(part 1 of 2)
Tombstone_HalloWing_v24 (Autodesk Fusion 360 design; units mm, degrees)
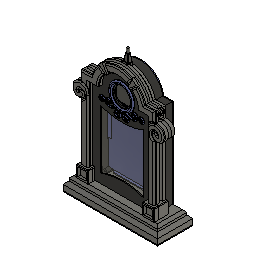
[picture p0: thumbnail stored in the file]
part number: FIDUCIAL_1MM
part number: MOUNTINGHOLE2.5
part number: SEWTAP_ALLILONG
part number: SEWTAPPCB_ALLIGATOR
part number: ALS-PT21
part number: 1M
part number: EAGLE
part number: ORANGE
part number: SPST_TACT-EVQQ2
part number: microUSB
part number: MCP73831T-2ACI/OT
part number: JSTPH
part number: WS2812B_4020
part number: FEATHERWING_SMTDUALNOHOLES
part number: BSS138
part number: JST PH 3
part number: MBR0540
part number: DMG3405
part number: 10K
part number: JST PH 4
parameter "wallThickness" = 1.5
parameter "M3hole" = 3
parameter "m25" = 2.5
parameter "gap" = 0.2
parameter "acrylicThickness" = 3
work_plane "WorkPlane1" AlongDistance -2
sketch "base profile" plane through (0, -2, 0) normal (0, 1, 0) x axis (1, 0, 0)
  line L1 (80, -14) -> (-80, -14)
  line L2 (80, 0) -> (80, -14)
  line L3 (-80, 0) -> (80, 0)
  line L4 (-80, -14) -> (-80, 0)
  line L5 (75, -22) -> (-75, -22)
  line L6 (75, -14) -> (75, -22)
  line L7 (-75, -14) -> (75, -14)
  line L8 (-75, -22) -> (-75, -14)
  line L9 (34, -168) -> (-34, -168)
  line L10 (-50, -168) -> (-34, -168)
  line L11 (-50, -22) -> (-50, -168)
  line L12 (0, -22) -> (0, -202)
  line L13 (50, -168) -> (34, -168)
  line L14 (50, -22) -> (50, -168)
  curve K1 (0, -153) -> (0, -183)
  curve K2 (-14, -168) -> (14, -168)
  arc A1 centre (0, -168) radius 34 clockwise from (34, -168) to (-34, -168)
  closed curve K3 centre (0, -168)
  point P1 (0, 0)
  point P14 (-50, -22)
  point P15 (0, -202)
  point P16 (0, -22)
  point P12 (0, -168)
  point P18 (50, -22)
  point P20 (0, -183)
  point P21 (0, -153)
  point P22 (14, -168)
  point P23 (-14, -168)
  point P4 (80, 0)
  point P5 (-80, 0)
  point P3 (80, -14)
  point P7 (75, -22)
  point P8 (75, -14)
  point P10 (-34, -168)
  point P13 (-50, -168)
  horizontal L1
  vertical L2
  horizontal L3
  vertical L4
  horizontal L5
  vertical L6
  horizontal L7
  vertical L8
  midpoint L1 L7
  midpoint P1 L3
  horizontal L9
  parallel L9 L10
  coincident L5 P14
  perpendicular L5 L11
  midpoint A1 P15
  midpoint L5 P16
  vertical L12
  coincident P12 L9
  parallel L9 L13
  coincident L5 P18
  perpendicular L5 L14
  vertical K1
  coincident K3 P20
  coincident K3 P21
  coincident K3 P22
  coincident K3 P23
  collinear L12 K1
  collinear L9 K2
  dimension "d1" distance P4 P5 = 160
  dimension "d2" distance L2 L6 = 5
  dimension "d3" distance P3 P4 = 14
  dimension "d4" distance P7 P8 = 8
  dimension "d5" distance P15 P16 = 180
  dimension "d6" distance P10 P13 = 16
  dimension "d7" distance L11 L12 = 50
  dimension "d8" distance L12 L14 = 50
  dimension "d9" = 28
  dimension "d10" distance K3 = 30
extrude "Extrude1" new body sketch "base profile" profile of L5 A1 L10 L11 L13 L14 K3 along normal blind 1.5 (= "wallThickness")
sketch "offset" plane through (0, 0, 0) normal (0, 1, 0) x axis (1, 0, 0)
  line L1 (-50, -168) -> (-34, -168)
  line L2 (-50, -22) -> (-50, -168)
  line L3 (50, -22) -> (-50, -22)
  line L4 (50, -168) -> (50, -22)
  line L5 (34, -168) -> (50, -168)
  line L6 (44.4072, -180) -> (62, -180)
  line L7 (-62, -180) -> (-44.4072, -180)
  line L8 (-62, -10) -> (-62, -180)
  line L9 (62, -10) -> (-62, -10)
  line L10 (62, -180) -> (62, -10)
  line L11 (36.8782, -171) -> (53, -171)
  line L12 (-53, -171) -> (-36.8782, -171)
  line L13 (-53, -19) -> (-53, -171)
  line L14 (53, -19) -> (-53, -19)
  line L15 (53, -171) -> (53, -19)
  line L16 (62, -22) -> (-62, -22)
  closed curve K1 centre (0, -168)
  arc A1 centre (0, -168) radius 34 clockwise from (34, -168) to (-34, -168)
  arc A2 centre (0, -168) radius 46 clockwise from (44.4072, -180) to (-44.4072, -180)
  arc A3 centre (0, -168) radius 37 clockwise from (36.8782, -171) to (-36.8782, -171)
  point P23 (-62, -22)
  point P24 (62, -22)
  coincident L8 P23
  coincident L10 P24
  perpendicular L10 L16
  collinear L3 L16
  dimension "d19" = 12
  dimension "d20" = 3
extrude "Extrude1" new body sketch "offset" profile of A1 L1 L2 L4 L5 L10 L8 L7 A2 L6 L15 L13 L12 A3 L11 L16 distance 10
extrude "Extrude2" sketch "offset" profile of A1 L1 L2 L4 L5 L15 L13 L12 A3 L11 L16 blind -12
sketch "outline" plane through (0, 10, 0) normal (0, 1, 0) x axis (-1, 0, 0)
  line L1 (-53, 171) -> (-53, 22)
  line L2 (-36.8782, 171) -> (-53, 171)
  line L3 (53, 171) -> (36.8782, 171)
  line L4 (53, 22) -> (53, 171)
  line L5 (62, 22) -> (53, 22)
  line L6 (62, 180) -> (62, 22)
  line L7 (44.4072, 180) -> (62, 180)
  line L8 (-62, 180) -> (-44.4072, 180)
  line L9 (-62, 22) -> (-62, 180)
  line L10 (-53, 22) -> (-62, 22)
  line L11 (-53, 22) -> (53, 22)
  arc A1 centre (0, 168) radius 37 clockwise from (-36.8782, 171) to (36.8782, 171)
  arc A2 centre (0, 168) radius 46 clockwise from (-44.4072, 180) to (44.4072, 180)
  point P8 (53, 22)
  point P15 (53, 22)
  point P2 (-53, 22)
  point P16 (-53, 22)
  coincident P8 P15
  coincident P2 P16
extrude "Extrude1" new body sketch "outline" profile of L1 L2 A1 L3 L4 L11 along normal blind 18
sketch "base" plane through (0, 28, 0) normal (0, 1, 0) x axis (-1, 0, 0)
  line L1 (-53, 171) -> (-36.8782, 171)
  line L2 (-53, 22) -> (-53, 171)
  line L3 (53, 22) -> (-53, 22)
  line L4 (53, 171) -> (53, 22)
  line L5 (36.8782, 171) -> (53, 171)
  arc A1 centre (0, 168) radius 37 clockwise from (-36.8782, 171) to (36.8782, 171)
shell "Shell1" outerThickness 2
sketch "open" plane through (0, -0.5, 0) normal (0, 1, 0) x axis (-1, 0, 0)
  line L1 (-50, 168) -> (-34, 168)
  line L2 (-50, 22) -> (-50, 168)
  line L3 (50, 22) -> (-50, 22)
  line L4 (50, 168) -> (50, 22)
  line L5 (34, 168) -> (50, 168)
  line L6 (36, 154) -> (-36, 154)
  line L7 (36, 36) -> (36, 154)
  line L8 (-36, 36) -> (36, 36)
  line L9 (-36, 154) -> (-36, 36)
  line L10 (0, 22) -> (0, 36)
  line L11 (0, 154) -> (0, 230)
  line L12 (0, 0) -> (0, -56)
  closed curve K1 centre (0, 168)
  arc A1 centre (0, 168) radius 34 clockwise from (-34, 168) to (34, 168)
  circle C1 centre (0, 230) radius 100
  circle C2 centre (0, -56) radius 100
  point P13 (0, 36)
  point P14 (0, 22)
  point P15 (0, 230)
  point P16 (0, 230)
  point P17 (0, 154)
  point P18 (0, -56)
  point P19 (0, -56)
  point P1 (0, 0)
  point P20 (0, 0)
  horizontal L6
  vertical L7
  horizontal L8
  vertical L9
  midpoint L8 P13
  midpoint L3 P14
  vertical L10
  coincident P15 P16
  midpoint L6 P17
  vertical L11
  coincident P18 P19
  coincident P1 P20
  vertical L12
  dimension "d27" distance L3 L8 = 14
  dimension "d28" distance L4 L7 = 14
  dimension "d29" distance L1 L6 = 14
  dimension "d30" diameter C1 = 200
  dimension "d31" distance P16 P17 = 76
  dimension "d32" diameter C2 = 200
  dimension "d33" distance P19 P20 = 56
  dimension "d93" = 1.5
extrude "Extrude2" cut sketch "open" profile of L7 L9 C1 C2 no distance stored
offset_faces "OffsetFaces1" distance 2.2
sketch "base hole" plane through (0, 0, 22) normal (0, 0, -1) x axis (1, 0, 0)
  line L1 (53, -10) -> (53, 2)
  line L2 (62, -10) -> (53, -10)
  line L3 (62, 10) -> (62, -10)
  line L4 (50, 10) -> (62, 10)
  line L5 (50, 2) -> (50, 10)
  line L6 (53, 2) -> (50, 2)
  line L7 (57.5, 10) -> (57.5, -10)
  circle C1 centre (57.5, 0) radius 1.4
  circle C2 centre (57.5, 0) radius 3.5
  point P8 (57.5, -10)
  point P9 (57.5, 10)
  point P10 (57.5, 0)
  midpoint L2 P8
  coincident L4 P9
  perpendicular L4 L7
  coincident L7 P10
  midpoint L7 P10
  concentric C1 C2
  dimension "d36" diameter C1 = 2.8 (= "M3hole - gap")
  dimension "d38" diameter C2 = 7
extrude "Extrude3" cut sketch "base hole" profile of C1 against normal blind 12
mirror "Mirror1" mirrorStitchTolerance 0.1
sketch "tabs" plane through (0, 10, 0) normal (0, 1, 0) x axis (-1, 0, 0)
  line L1 (-53, 171) -> (-53, 22)
  line L2 (-49, 150) -> (-54, 150)
  line L3 (-49, 143) -> (-49, 150)
  line L4 (-54, 143) -> (-49, 143)
  line L5 (-49, 50) -> (-54, 50)
  line L6 (-49, 43) -> (-49, 50)
  line L7 (-54, 43) -> (-49, 43)
  line L8 (-54, 146.5) -> (-54, 46.5)
  line L9 (-53, 96.5) -> (-54, 96.5)
  circle C1 centre (-54, 146.5) radius 1.5
  circle C2 centre (-54, 146.5) radius 3.5
  circle C3 centre (-54, 46.5) radius 1.5
  circle C4 centre (-54, 46.5) radius 3.5
  point P6 (-54, 150)
  point P9 (-54, 143)
  point P12 (-54, 50)
  point P15 (-54, 43)
  point P11 (-54, 46.5)
  point P16 (-54, 46.5)
  point P5 (-54, 146.5)
  point P17 (-54, 146.5)
  point P18 (-54, 96.5)
  point P19 (-53, 96.5)
  point P10 (-54, 46.5)
  concentric C1 C2
  coincident C2 P6
  horizontal L2
  perpendicular L2 L3
  coincident C2 P9
  tangent C2 L4
  tangent C2 L2
  perpendicular L3 L4
  concentric C3 C4
  coincident C4 P12
  tangent C4 L5
  perpendicular L5 L6
  coincident C4 P15
  tangent C4 L7
  perpendicular L6 L7
  vertical L6
  coincident P11 P16
  coincident P5 P17
  vertical L8
  midpoint L8 P18
  perpendicular L8 L9
  midpoint L1 P19
  dimension "d43" diameter C1 = 3
  dimension "d44" diameter C2 = 7
  dimension "d45" distance P5 L3 = 5
  dimension "d46" diameter C3 = 3
  dimension "d47" diameter C4 = 7
  dimension "d48" distance P10 L6 = 5
  dimension "d49" distance P16 P17 = 100
  dimension "d50" distance P18 P19 = 1
extrude "Extrude4" cut sketch "tabs" profile of C1 C2 L2 L3 L4 C3 C4 L5 L6 L7 to an object
extrude "Extrude5" sketch "tabs" profile of C1 C3 blind -6
offset_faces "OffsetFaces1" distance -0.4 (= "-( gap * 2 )")
mirror "Mirror3" mirrorStitchTolerance 0.1
fillet "Fillet2" radius 1
extrude "Extrude3" sketch "tabs" profile of C1 C2 L2 L3 L4 C3 C4 L5 L6 L7 no distance stored
offset_faces "OffsetFaces2" distance -0.25
mirror "Mirror1" mirrorStitchTolerance 0.1
fillet "Fillet1" radius 1 2
pcb "PCB1" BoardHeight 1.57 named "d1_1"
sketch "Sketch1" plane through (0, 0, 0) normal (0, 0, 1) x axis (1, 0, 0)
  line L1 (-1.57, 0.97) -> (-0.97, 0.97)
  line L2 (-1.57, 1.57) -> (-1.57, 0.97)
  line L3 (-0.97, 1.57) -> (-1.57, 1.57)
  line L4 (-0.97, 0.97) -> (-0.97, 1.57)
  line L5 (-1.57, 1.57) -> (-0.97, 0.97)
  line L6 (-0.97, 1.57) -> (-1.57, 0.97)
  line L7 (-2.54, 0) -> (0, 0)
  line L8 (-2.54, 2.54) -> (-2.54, 0)
  line L9 (0, 2.54) -> (-2.54, 2.54)
  line L10 (0, 0) -> (0, 2.54)
  point P6 (-1.27, 1.27)
  point P1 (0, 0)
  point P7 (0, 0)
  point P4 (-1.57, 1.57)
  point P5 (-0.97, 1.57)
  point P3 (-1.57, 0.97)
  perpendicular L1 L2
  parallel L1 L3
  parallel L2 L4
  horizontal L1
  coincident L5 P6
  coincident L6 P6
  horizontal L7
  vertical L8
  horizontal L9
  vertical L10
  coincident P1 P7
  dimension "d1_2" distance P4 P5 = 0.6
  dimension "d2_2" distance P3 P4 = 0.6
  dimension "d3_2" distance P1 P6 = 1.27
  dimension "d4_2" distance P1 P6 = 1.27
  dimension "d5_2" distance P6 L8 = 1.27
  dimension "d6_2" distance P6 L9 = 1.27
extrude "Extrude1" new body sketch "Sketch1" profile of L1 L2 L3 L4 L7 L8 L9 L10 along normal blind 4 named "d7_2"
chamfer "Chamfer1" distance 0.2 named "d15_2"
mirror "Mirror1"
combine "Combine1"
rectangular_pattern "R-Pattern1" uSpaceDistance 2.54 named "d12_2" vSpaceDistance 0 named "d13_2"
combine "Combine2"
mirror "Mirror2"
combine "Combine3"
sketch "Sketch1" plane through (0, 0, 0) normal (0, 0, 1) x axis (1, 0, 0)
  line L1 (2.5, -20.3) -> (-2.5, -20.3)
  line L2 (2.5, 20.3) -> (2.5, -20.3)
  line L3 (-2.5, 20.3) -> (2.5, 20.3)
  line L4 (-2.5, -20.3) -> (-2.5, 20.3)
  line L5 (2.5, 20.3) -> (-2.5, -20.3)
  line L6 (-2.5, 20.3) -> (2.5, -20.3)
  point P6 (0, 0)
  point P1 (0, 0)
  point P4 (2.5, 20.3)
  point P5 (-2.5, 20.3)
  point P3 (2.5, -20.3)
  perpendicular L1 L2
  parallel L1 L3
  parallel L2 L4
  horizontal L1
  coincident L5 P6
  coincident L6 P6
  coincident P1 P6
  dimension "d1_1" distance P4 P5 = 5
  dimension "d2_1" distance P3 P4 = 40.6
extrude "Extrude1" new body sketch "Sketch1" profile of L1 L2 L3 L4 along normal blind 4 named "d3_1"
sketch "Sketch2" plane through (0, 0, 4) normal (0, 0, 1) x axis (-1, 0, 0)
  line L1 (2.5, 20.3) -> (2.5, -20.3)
  line L2 (-2.5, 20.3) -> (2.5, 20.3)
  line L3 (-2.5, -20.3) -> (-2.5, 20.3)
  line L4 (2.5, -20.3) -> (-2.5, -20.3)
  line L5 (0.93, -19.33) -> (1.53, -19.33)
  line L6 (0.93, -18.73) -> (0.93, -19.33)
  line L7 (1.53, -18.73) -> (0.93, -18.73)
  line L8 (1.53, -19.33) -> (1.53, -18.73)
  line L9 (1.23, -18.73) -> (1.23, -19.33)
  line L10 (1.53, -19.03) -> (0.93, -19.03)
  point P10 (1.23, -19.33)
  point P11 (1.23, -18.73)
  point P12 (0.93, -19.03)
  point P13 (1.53, -19.03)
  point P6 (1.53, -19.33)
  point P7 (0.93, -19.33)
  point P9 (1.53, -18.73)
  horizontal L5
  vertical L6
  horizontal L7
  vertical L8
  midpoint L5 P10
  midpoint L7 P11
  midpoint L6 P12
  midpoint L8 P13
  dimension "d5_1" distance P6 P7 = 0.6
  dimension "d6_1" distance P6 P9 = 0.6
  dimension "d7_1" distance L4 L10 = 1.27
  dimension "d8_1" distance L1 L9 = 1.27
extrude "Extrude2" cut sketch "Sketch2" profile of L5 L6 L7 L8 against normal blind 4 named "d9_1"
chamfer "Chamfer1" distance 0.2 named "d11_1"
rectangular_pattern "R-Pattern1" CountV 16 named "d13_1" uSpaceDistance 2.54 named "d14_1" vSpaceDistance -2.54 named "d15_1"
as_built_joint "As-built2"
joint "Assemble1" alignAngle 180 named "d82_1" alignOffsetX 0 named "d83_1" alignOffsetY 0 named "d84_1" alignOffsetZ 0 named "d85_1"
joint "Assemble1" alignAngle 180 alignOffsetX 0 alignOffsetY 0 alignOffsetZ -3.6
sketch "holes" plane through (0, -0.5, 0) normal (0, 1, 0) x axis (-1, 0, 0)
  circle C1 centre (-9.017, 192.373) radius 1.25
  circle C2 centre (8.763, 192.373) radius 1.25
  circle C3 centre (-13.8, 192.063) radius 1.2
  circle C4 centre (-9.017, 146.653) radius 1.27
  circle C5 centre (8.763, 146.653) radius 1.27
  circle C6 centre (-9.017, 146.653) radius 1
  circle C7 centre (8.763, 146.653) radius 1
  circle C8 centre (-13.8, 192.063) radius 1.5
  circle C9 centre (-9.017, 192.373) radius 1.25
  circle C10 centre (8.763, 192.373) radius 1.25
  circle C11 centre (8.763, 146.653) radius 2.5
  circle C12 centre (-9.017, 146.653) radius 2.5
  circle C13 centre (8.763, 192.373) radius 2.75
  circle C14 centre (-9.017, 192.373) radius 2.75
  circle C15 centre (-13.8, 192.063) radius 3
  concentric C4 C6
  concentric C5 C7
  concentric C3 C8
  concentric C1 C9
  concentric C2 C10
  concentric C7 C11
  concentric C6 C12
  concentric C2 C13
  concentric C9 C14
  concentric C3 C15
  dimension "d75" diameter C6 = 2
  dimension "d76" diameter C7 = 2
  dimension "d77" distance C7 C11 = 1.5 (= "wallThickness")
  dimension "d78" distance C6 C12 = 1.5 (= "wallThickness")
  dimension "d79" diameter C9 = 2.5
  dimension "d80" diameter C10 = 2.5
  dimension "d81" distance C10 C13 = 1.5 (= "wallThickness")
  dimension "d82" distance C9 C14 = 1.5 (= "wallThickness")
  dimension "d83" diameter C8 = 3
  dimension "d84" distance C8 C15 = 1.5 (= "wallThickness")
extrude "Extrude4" add sketch "holes" profile of C6 C7 C8 C9 C10 C11 C12 C13 C14 C15 to an object
extrude "Extrude5" sketch "holes" profile of C6 C7 blind 2
extrude "Extrude6" cut sketch "holes" profile of C8 no distance stored
chamfer "Chamfer1" distance 1
extrude "Extrude7" add sketch "open" profile of K1 L6 along normal blind 1.5 (= "wallThickness")
chamfer "Chamfer2" distance 1.5 (= "wallThickness")
chamfer "Chamfer3" distance 1.5 (= "wallThickness")
work_plane "WorkPlane1" AlongDistance -0.5
sketch "Sketch1" plane through (0, -0.5, 0) normal (0, 1, 0) x axis (1, 0, 0)
  line L1 (-40, -139) -> (40, -139)
  line L2 (-40, -35) -> (-40, -139)
  line L3 (40, -35) -> (-40, -35)
  line L4 (40, -139) -> (40, -35)
  line L5 (0, 0) -> (0, -35)
  point P6 (0, -35)
  point P1 (0, 0)
  point P7 (0, 0)
  point P2 (40, -139)
  point P3 (-40, -139)
  point P5 (40, -35)
  horizontal L1
  vertical L2
  horizontal L3
  vertical L4
  midpoint L3 P6
  coincident P1 P7
  vertical L5
  dimension "d99" distance P2 P3 = 80
  dimension "d100" distance P2 P5 = 104
  dimension "d101" distance P6 P7 = 35
extrude "Extrude1" new body sketch "Sketch1" profile of L1 L2 L3 L4 along normal blind 3 (= "acrylicThickness")
work_plane "WorkPlane1" AlongDistance 35
sketch "holders" plane through (0, 0, 35) normal (0, 0, 1) x axis (1, 0, 0)
  line L1 (40.2, -0.5) -> (41.7, -0.5)
  line L2 (40.2, 4.5) -> (40.2, -0.5)
  line L3 (41.7, 4.5) -> (40.2, 4.5)
  line L4 (41.7, -0.5) -> (41.7, 4.5)
  line L5 (39.2, 3.5) -> (40.2, 4.5)
  line L6 (40.2, 2.5) -> (39.2, 3.5)
  line L7 (46.7, -0.5) -> (41.7, 4.5)
  line L8 (41.7, -0.5) -> (46.7, -0.5)
  line L9 (0, -0.5) -> (40.2, -0.5)
  line L10 (0, 0) -> (0, -0.5)
  line L11 (-25, -0.5) -> (25, -0.5)
  line L12 (-25, 2.5) -> (-25, -0.5)
  line L13 (25, 2.5) -> (-25, 2.5)
  line L14 (25, -0.5) -> (25, 2.5)
  line L15 (28, -0.5) -> (25, 2.5)
  line L16 (-28, -0.5) -> (-25, 2.5)
  line L17 (-25, -0.5) -> (-28, -0.5)
  point P7 (40.2, 2.5)
  point P1 (0, 0)
  point P10 (0, 0)
  point P9 (0, -0.5)
  point P15 (28, -0.5)
  point P14 (25, 2.5)
  point P16 (-25, 2.5)
  point P17 (-28, -0.5)
  point P4 (40.2, 4.5)
  point P5 (41.7, 4.5)
  point P2 (41.7, -0.5)
  point P3 (40.2, -0.5)
  point P11 (25, -0.5)
  point P13 (-25, 2.5)
  horizontal L1
  vertical L2
  horizontal L3
  vertical L4
  coincident L2 P7
  perpendicular L5 L6
  horizontal L8
  perpendicular L2 L9
  perpendicular L1 L10
  coincident P1 P10
  horizontal L11
  vertical L12
  horizontal L13
  vertical L14
  midpoint P9 L11
  coincident L9 P15
  symmetric L10 P14 P16
  symmetric L10 P15 P17
  dimension "d106" angle L2 L5 = 45
  dimension "d107" distance P4 P7 = 2
  dimension "d108" distance P4 P5 = 1.5 (= "wallThickness")
  dimension "d109" angle L4 L7 = 45
  dimension "d110" distance P2 P5 = 5
  dimension "d111" distance P9 P10 = 0.5
  dimension "d112" distance P3 P9 = 40.2 (= "40 mm + gap")
  dimension "d113" distance P11 P14 = 3
  dimension "d114" distance P13 P14 = 50
  dimension "d117" angle L9 L15 = 45
extrude "Extrude9" add sketch "holders" profile of L1 L2 L3 L4 L5 L6 L7 L8 along normal blind 8
extrude "Extrude10" sketch "holders" profile of L1 L2 L3 L4 L5 L6 L7 L8 blind -8
mirror "Mirror2" mirrorStitchTolerance 0.1
extrude "Extrude8" add sketch "holders" profile of L11 L12 L13 L14 no distance stored
work_plane "WorkPlane1" AlongDistance 182 (= "22.00 mm + 160 mm")
sketch "usb hole" plane through (0, 0, 182) normal (0, 0, 1) x axis (1, 0, 0)
  line L1 (8, 8) -> (8, 18)
  line L2 (-8, 18) -> (-8, 8)
  line L3 (8, 18) -> (-8, 18)
  line L4 (0, 8) -> (0, 18)
  line L5 (0, 8) -> (0, 0)
  arc A1 centre (0, 8) radius 8 clockwise from (8, 8) to (-8, 8)
  point P7 (0, 18)
  point P5 (0, 8)
  point P8 (0, 8)
  point P1 (0, 0)
  point P9 (0, 0)
  point P10 (0, 8)
  point P2 (8, 18)
  point P6 (-8, 18)
  vertical L1
  tangent L1 A1
  tangent A1 L2
  parallel L1 L2
  perpendicular L1 L3
  midpoint L3 P7
  coincident P5 P8
  coincident P1 P9
  coincident P5 P10
  vertical L5
  dimension "d132" distance P7 P8 = 10
  dimension "d133" distance P2 P6 = 16
  dimension "d134" distance P9 P10 = 8
extrude "Extrude7" cut sketch "usb hole" profile of L1 A1 L2 L3 no distance stored
sketch "Sketch1" plane through (0, 0, 0) normal (0, 0, 1) x axis (1, 0, 0)
  line L1 (17.9, 0) -> (0, 0)
  line L2 (17.9, 10.8) -> (17.9, 0)
  line L3 (0, 10.8) -> (17.9, 10.8)
  line L4 (0, 0) -> (0, 10.8)
  point P1 (0, 0)
  point P2 (0, 0)
  point P3 (17.9, 0)
  point P5 (0, 10.8)
  horizontal L1
  vertical L2
  horizontal L3
  vertical L4
  coincident P1 P2
  dimension "d1_3" distance P2 P3 = 17.9
  dimension "d2_3" distance P2 P5 = 10.8
extrude "Extrude1" new body sketch "Sketch1" along normal blind 7.9 named "d3_3"
chamfer "Chamfer1" distance 2.2 named "d5_3"
sketch "Sketch2" plane through (0, 0, 0) normal (-1, 0, 0) x axis (0, -1, 0)
  line L1 (-2.2, 7.9) -> (0, 5.7)
  line L2 (-8.6, 7.9) -> (-2.2, 7.9)
  line L3 (-10.8, 5.7) -> (-8.6, 7.9)
  line L4 (-10.8, 0) -> (-10.8, 5.7)
  line L5 (0, 0) -> (-10.8, 0)
  line L6 (0, 5.7) -> (0, 0)
  line L7 (-5.4, 0) -> (-5.4, 7.9)
  line L8 (0, 3.95) -> (-5.4, 3.95)
  line L9 (-8.8, 3.05) -> (-2, 3.05)
  line L10 (-8.8, 4.85) -> (-8.8, 3.05)
  line L11 (-2, 4.85) -> (-8.8, 4.85)
  line L12 (-2, 3.05) -> (-2, 4.85)
  line L13 (-8.8, 4.85) -> (-2, 3.05)
  line L14 (-2, 4.85) -> (-8.8, 3.05)
  point P8 (-5.4, 7.9)
  point P9 (-5.4, 0)
  point P11 (0, 3.95)
  point P16 (-5.4, 3.95)
  point P10 (-5.4, 3.95)
  point P14 (-8.8, 4.85)
  point P15 (-2, 4.85)
  point P13 (-8.8, 3.05)
  midpoint L2 P8
  midpoint L5 P9
  coincident L6 P11
  perpendicular L6 L8
  perpendicular L9 L10
  parallel L9 L11
  parallel L10 L12
  horizontal L9
  coincident L13 P16
  coincident L14 P16
  coincident P10 P16
  dimension "d6_3" distance P14 P15 = 6.8
  dimension "d7_3" distance P13 P14 = 1.8
extrude "Extrude2" add sketch "Sketch2" profile of L9 L10 L11 L12 along normal blind 6 named "d8_3"
chamfer "Chamfer2" distance 1 named "d10_3"
sketch "Sketch3" plane through (17.9, 0, 0) normal (1, 0, 0) x axis (0, 1, 0)
  line L1 (0, 5.7) -> (2.2, 7.9)
  line L2 (0, 0) -> (0, 5.7)
  line L3 (10.8, 0) -> (0, 0)
  line L4 (10.8, 5.7) -> (10.8, 0)
  line L5 (8.6, 7.9) -> (10.8, 5.7)
  line L6 (2.2, 7.9) -> (8.6, 7.9)
  line L7 (5.4, 0) -> (5.4, 7.9)
  line L8 (10.8, 3.95) -> (5.4, 3.95)
  line L9 (1.6, 0.85) -> (9.2, 0.85)
  line L10 (1.6, 7.05) -> (1.6, 0.85)
  line L11 (9.2, 7.05) -> (1.6, 7.05)
  line L12 (9.2, 0.85) -> (9.2, 7.05)
  line L13 (1.6, 7.05) -> (9.2, 0.85)
  line L14 (9.2, 7.05) -> (1.6, 0.85)
  point P8 (5.4, 7.9)
  point P9 (5.4, 0)
  point P11 (10.8, 3.95)
  point P16 (5.4, 3.95)
  point P10 (5.4, 3.95)
  point P13 (1.6, 0.85)
  point P14 (1.6, 7.05)
  point P15 (9.2, 7.05)
  midpoint L6 P8
  midpoint L3 P9
  coincident L4 P11
  perpendicular L4 L8
  perpendicular L9 L10
  parallel L9 L11
  parallel L10 L12
  horizontal L9
  coincident L13 P16
  coincident L14 P16
  coincident P10 P16
  dimension "d11_3" distance P13 P14 = 6.2
  dimension "d12_3" distance P14 P15 = 7.6
extrude "Extrude3" add sketch "Sketch3" profile of L9 L10 L11 L12 along normal blind 12 named "d13_3" taper -3 named "d14_3"
sketch "Sketch4" plane through (29.9, 0, 0) normal (1, 0, 0) x axis (0, 1, 0)
  line L1 (8.5711, 6.4211) -> (8.5711, 1.4789)
  line L2 (2.2289, 6.4211) -> (8.5711, 6.4211)
  line L3 (2.2289, 1.4789) -> (2.2289, 6.4211)
  line L4 (8.5711, 1.4789) -> (2.2289, 1.4789)
  line L5 (5.4, 1.4789) -> (5.4, 6.4211)
  line L6 (8.5711, 3.95) -> (2.2289, 3.95)
  circle C1 centre (5.4, 3.95) radius 1.9
  point P6 (5.4, 6.4211)
  point P7 (5.4, 1.4789)
  point P8 (2.2289, 3.95)
  point P9 (8.5711, 3.95)
  point P10 (5.4, 3.95)
  midpoint L2 P6
  midpoint L4 P7
  midpoint L3 P8
  midpoint L1 P9
  midpoint L5 P10
  dimension "d15_3" diameter C1 = 3.8
extrude "Extrude4" add sketch "Sketch4" profile of C1 along normal blind 8 named "d16_1"
fillet "Fillet1" radius 1 named "d18_2"
joint "Assemble1" alignAngle 90 alignOffsetX 0 alignOffsetY 0 alignOffsetZ 0
fillet "Fillet4" radius 2
chamfer "Chamfer1" distance 2
extrude "Extrude1" new body sketch "base profile" profile of L1 L2 L3 L4 L7 distance 30 from offset 10
extrude "Extrude2" add sketch "base profile" profile of L1 L5 L6 L7 L8 distance 25 from offset 10
chamfer "Chamfer1" distance 4
chamfer "Chamfer2" distance 5
shell "Shell1" innerThickness 1.5 (= "wallThickness")
sketch "holes frame" plane through (0, 0, 20.5) normal (0, 0, -1) x axis (1, 0, 0)
  line L1 (-52, -1) -> (-43, -1)
  line L2 (-52, -8) -> (-52, -1)
  line L3 (-43, -8) -> (-52, -8)
  line L4 (-43, -1) -> (-43, -8)
  circle C1 centre (-57.5, 0) radius 1.4
  circle C2 centre (57.5, 0) radius 1.4
  circle C3 centre (57.5, 0) radius 1.75
  circle C4 centre (-57.5, 0) radius 1.75
  point P6 (-43, -1)
  point P7 (-52, -1)
  point P9 (-43, -8)
  point P1 (0, 0)
  concentric C2 C3
  concentric C1 C4
  horizontal L1
  vertical L2
  horizontal L3
  vertical L4
  dimension "d151" diameter C3 = 3.5
  dimension "d152" diameter C4 = 3.5
  dimension "d155" distance P6 P7 = 9
  dimension "d156" distance P6 P9 = 7
  dimension "d157" distance P1 L4 = 43
  dimension "d159" distance P1 L1 = 1
extrude "Extrude3" cut sketch "holes frame" profile of C3 C4 L1 L2 L3 L4 no distance stored
fillet "Fillet1" radius 1
sketch "top lip extrude" plane through (0, 10, 0) normal (0, -1, 0) x axis (1, 0, 0)
  line L1 (36.8782, 171) -> (-36.8782, 171)
  line L2 (0, 171) -> (0, 168)
  line L3 (-32.0429, 186.5) -> (0, 168)
  line L4 (32.0429, 186.5) -> (0, 168)
  arc A1 centre (0, 168) radius 37 clockwise from (-36.8782, 171) to (36.8782, 171)
  arc A2 centre (0, 168) radius 35 clockwise from (-34.8848, 170.8378) to (34.8848, 170.8378)
  point P3 (-36.8782, 171)
  point P8 (-36.8782, 171)
  point P2 (36.8782, 171)
  point P9 (36.8782, 171)
  point P4 (0, 168)
  point P10 (0, 168)
  point P11 (0, 171)
  point P12 (0, 168)
  point P13 (-32.0429, 186.5)
  point P14 (0, 168)
  point P15 (32.0429, 186.5)
  coincident P3 P8
  coincident P2 P9
  coincident P4 P10
  midpoint L1 P11
  coincident P4 P12
  coincident A1 P13
  symmetric L2 P12 P14
  symmetric L2 P13 P15
  dimension "d182" = -2
  dimension "d183" angle L2 L3 = 60
extrude "Extrude4" add sketch "top lip extrude" profile of A1 A2 L3 L4 blind 6 from offset -3
offset_faces "OffsetFaces3"
chamfer "Chamfer1" distance 2
offset_faces "OffsetFaces4" distance -0.3
sketch "base tabs" plane through (0, 0, 22) normal (0, 0, 1) x axis (-1, 0, 0)
  line L1 (-53, -28) -> (-53, -10)
  line L2 (0, -14) -> (0, 0)
  line L3 (-53, -19) -> (-49, -19)
  line L4 (-45.25, -28) -> (-53, -28)
  line L5 (-45.25, -14.4745) -> (-45.25, -28)
  line L6 (-53, -10) -> (-45.25, -14.4745)
  line L7 (53, -28) -> (53, -10)
  line L8 (45.25, -28) -> (53, -28)
  line L9 (45.25, -14.4745) -> (45.25, -28)
  line L10 (53, -10) -> (45.25, -14.4745)
  circle C1 centre (-49, -19) radius 1.75
  circle C2 centre (-49, -19) radius 3.75
  circle C3 centre (49, -19) radius 1.75
  circle C4 centre (49, -19) radius 3.75
  point P1 (0, 0)
  point P4 (0, 0)
  point P7 (-49, -19)
  point P8 (-49, -19)
  point P9 (-53, -19)
  point P3 (-53, -28)
  point P12 (-53, -28)
  point P2 (-53, -10)
  point P15 (-53, -10)
  point P16 (53, -10)
  point P17 (53, -28)
  point P18 (53, -28)
  point P13 (-45.25, -28)
  point P19 (45.25, -28)
  point P14 (-45.25, -14.4745)
  point P20 (45.25, -14.4745)
  point P21 (53, -10)
  coincident P1 P4
  vertical L2
  concentric C1 C2
  coincident P7 P8
  midpoint L1 P9
  horizontal L3
  symmetric L2 C1 C3
  symmetric L2 C2 C4
  coincident P3 P12
  perpendicular L1 L4
  perpendicular L4 L5
  coincident P2 P15
  tangent C2 L5
  symmetric P2 L2 P16
  symmetric P3 L2 P17
  symmetric L2 P12 P18
  symmetric L2 P13 P19
  symmetric L2 P14 P20
  symmetric L2 P15 P21
  dimension "d165" diameter C1 = 3.5
  dimension "d166" distance C1 C2 = 2
  dimension "d217" angle L5 L6 = 120
  dimension "d218" distance P8 P9 = 4
extrude "Extrude2" add sketch "base tabs" profile of L1 C1 C2 C3 C4 L4 L5 L6 L7 L8 L9 L10 along normal blind 2
extrude "Extrude4" cut sketch "base tabs" profile of C1 C3 no distance stored
extrude "Extrude3" cut sketch "usb hole" profile of L1 A1 L2 L3 along normal blind 25
fillet "Fillet1" radius 3
offset_faces "OffsetFaces1" distance 5
offset_faces "OffsetFaces2" distance 2
fillet "Fillet2" radius 2
work_plane "WorkPlane2"
sketch "snaps" plane through (53.6, -1.25, 96.5) normal (0, 0, 1) x axis (1, 0, 0)
  line L1 (-1.6, 10.25) -> (-0.6, 9.25)
  line L2 (-0.6, 11.25) -> (-1.6, 10.25)
  line L3 (-0.6, 9.25) -> (-0.6, 11.25)
  line L4 (-1.6607, 8.1893) -> (-0.6, 9.25)
  line L5 (-3.7213, 10.25) -> (-1.6607, 8.1893)
  line L6 (-0.6, 13.3713) -> (-3.7213, 10.25)
  line L7 (-0.6, 11.25) -> (-0.6, 13.3713)
  line L8 (-0.6, 27.25) -> (-0.6, 29.25)
  line L9 (-1.6, 28.25) -> (-0.6, 27.25)
  line L10 (-0.6, 29.25) -> (-1.6, 28.25)
  point P4 (-0.6, 11.25)
  point P8 (-0.6, 11.25)
  point P9 (-0.6, 29.25)
  point P10 (-0.6, 29.25)
  point P2 (-0.6, 9.25)
  point P5 (-1.6607, 8.1893)
  point P11 (-0.6, 27.25)
  vertical L3
  perpendicular L1 L4
  perpendicular L4 L5
  perpendicular L5 L6
  parallel L3 L7
  perpendicular L1 L2
  coincident P4 P8
  coincident P9 P10
  vertical L8
  perpendicular L9 L10
  dimension "d192" distance P2 P4 = 2
  dimension "d193" angle L2 L3 = 45
  dimension "d194" distance P2 P5 = 1.5 (= "wallThickness")
  dimension "d196" distance L2 L6 = 1.5 (= "wallThickness")
  dimension "d206" angle L8 L10 = 45
  dimension "d207" distance P10 P11 = 2
extrude "Extrude5" add sketch "snaps" profile of L1 L2 L4 L5 L6 L7 L8 L9 L10 distance 30
offset_faces "OffsetFaces5" distance 0.2 (= "gap")
offset_faces "OffsetFaces6"
fillet "Fillet3" radius 0.5
draft "Draft2" Angle1 45 Angle2 0
mirror "Mirror1" mirrorStitchTolerance 0.1
sketch "top nub" plane through (0, 0, 0) normal (1, 0, 0) x axis (0, 1, 0)
  line L1 (28, 171) -> (28, 205)
  line L2 (26, 205) -> (28, 205)
  line L3 (27, 204) -> (26, 205)
  line L4 (28, 205) -> (27, 204)
  point P2 (28, 205)
  point P4 (28, 205)
  point P5 (26, 205)
  coincident P2 P4
  perpendicular L1 L2
  perpendicular L3 L4
  dimension "d208" angle L2 L4 = 45
  dimension "d209" distance P4 P5 = 2
sweep "Sweep1" sketch "top nub" TwistAngle 0 TaperAngle 0
fillet "Fillet4" radius 3
extrude "Extrude1" new body sketch "base" along normal blind 1.5 (= "wallThickness")
offset_faces "OffsetFaces1" distance 2
sketch "snaps" plane through (53.6, -1.25, 96.5) normal (0, 0, 1) x axis (1, 0, 0)
  line L1 (-4.7213, 29.25) -> (1.4, 29.25)
  line L2 (-0.6, 27.25) -> (-0.6, 29.25)
  line L3 (-1.6, 28.25) -> (-0.6, 27.25)
  line L4 (-0.6, 29.25) -> (-1.6, 28.25)
  line L5 (-1.6607, 26.1893) -> (-0.6, 27.25)
  line L6 (-4.7213, 29.25) -> (-1.6607, 26.1893)
  point P2 (1.4, 29.25)
  point P3 (1.4, 29.25)
  point P5 (-0.6, 29.25)
  point P6 (-0.6, 27.25)
  point P8 (-1.6607, 26.1893)
  coincident P2 P3
  horizontal L1
  coincident L1 P5
  perpendicular L1 L2
  perpendicular L3 L4
  perpendicular L3 L5
  perpendicular L5 L6
  dimension "d227" distance P5 P6 = 2
  dimension "d228" angle L2 L3 = 45
  dimension "d229" distance P6 P8 = 1.5 (= "wallThickness")
  dimension "d230" distance P3 L2 = 2
extrude "Extrude2" add sketch "snaps" profile of L1 L3 L4 L5 L6 distance 30
offset_faces "OffsetFaces2" distance 0.2 (= "gap")
offset_faces "OffsetFaces3"
draft "Draft1" Angle1 45 Angle2 0
fillet "Fillet1" radius 0.5
mirror "Mirror1" mirrorStitchTolerance 0.1
sketch "top snap" plane through (0, 0, 0) normal (1, 0, 0) x axis (0, 1, 0)
  line L1 (28, 207) -> (28, 173)
  line L2 (26, 205) -> (28, 205)
  line L3 (27, 204) -> (26, 205)
  line L4 (28, 205) -> (27, 204)
  line L5 (24.9393, 203.9393) -> (26, 205)
  line L6 (28, 200.8787) -> (24.9393, 203.9393)
  point P4 (28, 205)
  point P8 (28, 200.8787)
  point P3 (28, 207)
  point P5 (26, 205)
  point P7 (24.9393, 203.9393)
  coincident L1 P4
  perpendicular L1 L2
  perpendicular L3 L4
  perpendicular L3 L5
  coincident L1 P8
  perpendicular L5 L6
  dimension "d240" distance P3 L2 = 2
  dimension "d241" distance P4 P5 = 2
  dimension "d242" angle L2 L3 = 45
  dimension "d243" distance P5 P7 = 1.5 (= "wallThickness")
sweep "Sweep1" sketch "top snap" TwistAngle 0 TaperAngle 0
offset_faces "OffsetFaces4" distance 0.2 (= "gap")
offset_faces "OffsetFaces5"
fillet "Fillet2" radius 0.5
sketch "nubs" plane through (0, 0, 0) normal (1, 0, 0) x axis (0, 1, 0)
  line L1 (-20.5, 0) -> (-20.5, 2)
  line L2 (-19.5, 1) -> (-20.5, 0)
  line L3 (-20.5, 2) -> (-19.5, 1)
  line L4 (0, 0) -> (-20.5, 0)
  line L5 (0, 0) -> (36.5, 0)
  line L6 (36.5, 2) -> (36.5, 0)
  line L7 (35.5, 1) -> (36.5, 2)
  line L8 (36.5, 0) -> (35.5, 1)
  point P1 (0, 0)
  point P5 (0, 0)
  point P7 (0, 0)
  point P6 (36.5, 0)
  point P8 (36.5, 0)
  point P11 (36.5, 0)
  point P2 (-20.5, 2)
  point P3 (-20.5, 0)
  point P9 (36.5, 2)
  vertical L1
  perpendicular L2 L3
  coincident P1 P5
  horizontal L4
  coincident P1 P7
  horizontal L5
  coincident P6 P8
  perpendicular L5 L6
  coincident P8 P11
  perpendicular L7 L8
  dimension "d259" angle L1 L2 = 45
  dimension "d260" distance P2 P3 = 2
  dimension "d262" distance P3 P5 = 20.5
  dimension "d267" angle L6 L8 = 45
  dimension "d268" distance P6 P9 = 2
extrude "Extrude5" add sketch "nubs" profile of L1 L2 L3 L6 L7 L8 distance 20 from offset 40
mirror "Mirror1" mirrorStitchTolerance 0.1
sketch "wire channel" plane through (0, 0, 96.5) normal (0, 0, 1) x axis (1, 0, 0)
  line L1 (0, 3) -> (-54, 3)
  line L2 (0, 0) -> (0, 3)
  line L3 (-52.5, 5.5) -> (-54.7059, 4.3235)
  line L4 (-52.5, 3) -> (-52.5, 5.5)
  circle C1 centre (-54, 3) radius 1.5
  point P2 (-54, 3)
  point P3 (-54, 3)
  point P1 (0, 0)
  point P5 (0, 0)
  point P6 (-54.7059, 4.3235)
  point P8 (-52.5, 3)
  point P4 (0, 3)
  point P7 (-52.5, 5.5)
  coincident P2 P3
  horizontal L1
  coincident P1 P5
  perpendicular L1 L2
  coincident C1 P6
  tangent C1 L3
  coincident L1 P8
  coincident C1 P8
  tangent C1 L4
  dimension "d282" diameter C1 = 3
  dimension "d283" distance P4 P5 = 3
  dimension "d287" distance P3 P4 = 54
  dimension "d322" distance P7 P8 = 2.5
extrude "Extrude8" cut sketch "wire channel" profile of C1 L3 L4 distance 48
sketch "base" plane through (0, 0, 0) normal (0, 0, -1) x axis (1, 0, 0)
  line L1 (-80, -38) -> (-80, 22)
  line L2 (80, -38) -> (-80, -38)
  line L3 (80, 22) -> (80, -38)
  line L4 (-80, 22) -> (80, 22)
  line L5 (6, 16) -> (74, 16)
  line L6 (6, -32) -> (6, 16)
  line L7 (74, -32) -> (6, -32)
  line L8 (74, 16) -> (74, -32)
  line L9 (0, -38) -> (0, 22)
  line L10 (0, -8) -> (6, -8)
  line L11 (-74, -32) -> (-6, -32)
  line L12 (-74, 16) -> (-74, -32)
  line L13 (-6, 16) -> (-74, 16)
  line L14 (-6, -32) -> (-6, 16)
  line L15 (-74, -2) -> (74, -2)
  line L16 (-74, -14) -> (74, -14)
  line L17 (76.8, 7) -> (78.3, 7)
  line L18 (76.8, -23) -> (76.8, 7)
  line L19 (78.3, -23) -> (76.8, -23)
  line L20 (78.3, 7) -> (78.3, -23)
  line L21 (-76.8, 7) -> (-78.3, 7)
  line L22 (-76.8, -23) -> (-76.8, 7)
  line L23 (-78.3, -23) -> (-76.8, -23)
  line L24 (-78.3, 7) -> (-78.3, -23)
  line L25 (78.3, -8) -> (80, -8)
  point P10 (0, 22)
  point P11 (0, -38)
  point P12 (6, -8)
  point P13 (0, -8)
  point P6 (74, 16)
  point P16 (-74, 16)
  point P7 (6, 16)
  point P17 (-6, 16)
  point P8 (6, -32)
  point P14 (-6, -32)
  point P9 (74, -32)
  point P15 (-74, -32)
  point P18 (74, -2)
  point P19 (-74, -2)
  point P20 (74, -14)
  point P21 (-74, -14)
  point P22 (78.3, 7)
  point P26 (-78.3, 7)
  point P23 (76.8, 7)
  point P27 (-76.8, 7)
  point P24 (76.8, -23)
  point P28 (-76.8, -23)
  point P25 (78.3, -23)
  point P29 (-78.3, -23)
  point P30 (80, -8)
  point P31 (78.3, -8)
  horizontal L5
  vertical L6
  horizontal L7
  vertical L8
  midpoint L4 P10
  midpoint L2 P11
  midpoint L6 P12
  midpoint L9 P13
  horizontal L10
  symmetric P6 L9 P16
  symmetric P7 L9 P17
  symmetric P8 L9 P14
  symmetric P9 L9 P15
  coincident L8 P18
  coincident L12 P19
  perpendicular L12 L15
  symmetric L10 P18 P20
  symmetric L10 P19 P21
  horizontal L17
  vertical L18
  horizontal L19
  vertical L20
  symmetric L9 P22 P26
  symmetric L9 P23 P27
  symmetric L9 P24 P28
  symmetric L9 P25 P29
  midpoint L3 P30
  midpoint L20 P31
  horizontal L25
  dimension "d306" distance P12 P13 = 6
  dimension "d307" distance L4 L5 = 6
  dimension "d308" distance L3 L8 = 6
  dimension "d309" distance L10 L15 = 6
  dimension "d313" distance L3 L20 = 1.7 (= "wallThickness + gap")
  dimension "d314" distance P22 P23 = 1.5 (= "wallThickness")
  dimension "d315" distance P22 P25 = 30
extrude "Extrude2" new body sketch "base" profile of L1 L2 L3 L4 along normal blind 1.5 (= "wallThickness")
sketch "snaps" plane through (0, 0, 0) normal (1, 0, 0) x axis (0, 1, 0)
  line L1 (35.5, 1) -> (36.5, 2)
  line L2 (36.5, 0) -> (35.5, 1)
  line L3 (36.5, 2) -> (36.5, 0)
  line L4 (35.4393, 3.0607) -> (36.5, 2)
  line L5 (32.3787, 0) -> (35.4393, 3.0607)
  line L6 (36.5, 0) -> (32.3787, 0)
  line L7 (0, 0) -> (32.3787, 0)
  line L8 (-20.5, 0) -> (0, 0)
  line L9 (-20.5, 2) -> (-20.5, 0)
  line L10 (-19.5, 1) -> (-20.5, 2)
  line L11 (-20.5, 0) -> (-19.5, 1)
  line L12 (-19.4393, 3.0607) -> (-20.5, 2)
  line L13 (-16.3787, 0) -> (-19.4393, 3.0607)
  point P1 (0, 0)
  point P7 (0, 0)
  point P8 (0, 0)
  point P13 (-16.3787, 0)
  point P2 (36.5, 2)
  point P4 (36.5, 0)
  point P5 (35.4393, 3.0607)
  point P9 (-20.5, 0)
  point P10 (-20.5, 2)
  point P12 (-19.4393, 3.0607)
  vertical L3
  perpendicular L1 L2
  perpendicular L1 L4
  perpendicular L4 L5
  horizontal L6
  coincident P1 P7
  horizontal L7
  coincident P1 P8
  parallel L7 L8
  perpendicular L8 L9
  perpendicular L10 L11
  perpendicular L10 L12
  coincident L8 P13
  perpendicular L12 L13
  dimension "d290" distance P2 P4 = 2
  dimension "d291" angle L2 L3 = 45
  dimension "d292" distance P2 P5 = 1.5 (= "wallThickness")
  dimension "d293" distance P1 L3 = 36.5
  dimension "d294" distance P8 P9 = 20.5
  dimension "d295" distance P9 P10 = 2
  dimension "d296" angle L9 L10 = 45
  dimension "d297" distance P10 P12 = 1.5 (= "wallThickness")
extrude "Extrude3" add sketch "snaps" profile of L1 L2 L4 L5 L6 L8 L10 L11 L12 L13 distance 20 from offset 40
offset_faces "OffsetFaces1" distance 0.2 (= "gap")
offset_faces "OffsetFaces2"
fillet "Fillet1" radius 0.5
mirror "Mirror1" mirrorStitchTolerance 0.1
extrude "Extrude4" cut sketch "base" profile of L5 L6 L7 L8 L11 L12 L13 L14 L15 L16 along normal blind 1.5 (= "wallThickness")
fillet "Fillet2" radius 1.5
extrude "Extrude5" add sketch "base" profile of L17 L18 L19 L20 against normal blind 3
draft "Draft1" Angle1 45 Angle2 0
mirror "Mirror2" mirrorStitchTolerance 0.1
fillet "Fillet2" radius 1
sketch "side nubs" plane through (53.6, -1.25, 96.5) normal (0, 0, 1) x axis (1, 0, 0)
  line L1 (-0.6, 9.25) -> (-0.6, 11.25)
  line L2 (-1.6, 10.25) -> (-0.6, 9.25)
  line L3 (-0.6, 11.25) -> (-1.6, 10.25)
  point P2 (-0.6, 11.25)
  point P3 (-0.6, 11.25)
  point P6 (-0.6, 11.25)
  point P4 (-0.6, 9.25)
  coincident P2 P3
  vertical L1
  coincident P2 P6
  perpendicular L2 L3
  dimension "d324" angle L1 L3 = 45
  dimension "d325" distance P3 P4 = 2
extrude "Extrude9" add sketch "side nubs" distance 30
mirror "Mirror4" mirrorStitchTolerance 0.1
sketch "bottom cubes" plane through (0, 0, 0) normal (0, 0, 1) x axis (1, 0, 0)
  line L1 (-46, -14) -> (-66, -14)
  line L2 (-46, 10) -> (-46, -14)
  line L3 (-66, 10) -> (-46, 10)
  line L4 (-66, -14) -> (-66, 10)
  line L5 (-62, 10) -> (-62, -10)
  line L6 (-50, -10) -> (-62, -10)
  line L7 (-50, -2) -> (-50, -10)
  line L8 (-50, -2) -> (-53, -2)
  line L9 (-53, -2) -> (-53, 10)
  line L10 (-53, -2) -> (-46, -2)
  circle C1 centre (-57.5, 0) radius 1.4
  point P7 (-62, 10)
  point P13 (-46, -2)
  point P14 (-53, -2)
  point P8 (-50, -10)
  horizontal L1
  vertical L2
  horizontal L3
  vertical L4
  coincident L3 P7
  coincident L2 P13
  coincident L9 P14
  perpendicular L9 L10
  collinear L8 L10
  dimension "d330" distance L4 L5 = 4
  dimension "d331" distance L1 L6 = 4
  dimension "d332" distance L2 P8 = 4
sketch "Sketch10" plane through (0, -10, 0) normal (0, -1, 0) x axis (1, 0, 0)
  line L1 (-62, 180) -> (-44.4072, 180)
  line L2 (-62, 22) -> (-62, 180)
  line L3 (-50, 168) -> (-50, 22)
  curve K1 (-66.307, 145.9052) -> (-50, 147.821)
  curve K2 (-66.2802, 135.9003) -> (-66.3338, 155.9102)
  curve K3 (-68.4606, 135.2725) -> (-68.307, 145.9052)
  curve K4 (-68.2714, 150.5672) -> (-68.3426, 141.2432)
  curve K5 (-72.4475, 135.8875) -> (-64.4737, 134.6575)
  curve K6 (-59, 137) -> (-75, 137)
  curve K7 (-50, 157.1733) -> (-50, 138.4687)
  line L4 (-66.307, 145.9052) -> (-68.307, 145.9052)
  curve K8 (-70.4849, 161.8019) -> (-55.7545, 161.8019)
  curve K9 (-78.826, 146.5895) -> (-74.2125, 160.3045)
  curve K10 (-56.924, 139.4503) -> (-55.3122, 145.24)
  curve K11 (-78.2112, 157.1557) -> (-48.0129, 146.7264)
  curve K12 (-81.1729, 154.0072) -> (-75.2495, 160.3042)
  curve K13 (-62.6417, 153.138) -> (-54.3322, 142.9104)
  point P7 (-50, 147.821)
  point P12 (-66.307, 145.9052)
  point P15 (-68.307, 145.9052)
  point P17 (-68.4606, 135.2725)
  point P10 (-67, 137)
  point P8 (-63.1197, 161.8019)
  point P9 (-76.5193, 153.447)
  point P30 (-56.1181, 142.3452)
  point P35 (-78.2112, 157.1557)
  point P11 (-58.4869, 148.0242)
  coincident L3 P7
  midpoint P12 K2
  midpoint P15 K4
  midpoint P17 K5
  midpoint P10 K6
  midpoint P7 K7
  vertical K7
  horizontal L4
  midpoint P8 K8
  midpoint P9 K9
  horizontal K8
  midpoint P30 K10
  midpoint P35 K12
  midpoint P11 K13
  dimension "d340" distance P12 P15 = 2
extrude "Extrude13" add sketch "Sketch10" profile of L2 K1 K3 L4 against normal blind 20
extrude "Extrude15" cut sketch "Sketch10" profile of L2 L3 K1 K3 L4 K11 against normal blind 2
mirror "Mirror6" mirrorStitchTolerance 0.1
fillet "Fillet8" radius 1
extrude "Extrude10" sketch "bottom cubes" profile of L1 L2 L3 L4 L5 L6 L7 L10 blind 20
mirror "Mirror5" mirrorStitchTolerance 0.1
chamfer "Chamfer7" distance 2
sketch "Sketch11" plane through (0, -14, 0) normal (0, -1, 0) x axis (1, 0, 0)
  line L1 (-46, 22) -> (-66, 22)
  line L2 (-46, 42) -> (-46, 22)
  line L3 (-66, 42) -> (-46, 42)
  line L4 (-66, 22) -> (-66, 42)
  line L5 (-49, 25) -> (-63, 25)
  line L6 (-49, 39) -> (-49, 25)
  line L7 (-63, 39) -> (-49, 39)
  line L8 (-63, 25) -> (-63, 39)
  dimension "d370" = -3
extrude "Extrude17" cut sketch "Sketch11" profile of L8 L7 L6 L5 against normal blind 2
chamfer "Chamfer12" distance 2
mirror "Mirror7" mirrorStitchTolerance 0.1
chamfer "Chamfer13" distance 1
sketch "Sketch12" plane through (0, 0, 0) normal (0, 1, 0) x axis (1, 0, 0)
  line L1 (-24.1234, -210.1567) -> (-33.3159, -202.4433)
  line L2 (-16, -196.0865) -> (-24.1234, -210.1567)
  line L3 (-20.8702, -192) -> (-16, -196.0865)
  line L4 (-33.3159, -202.4433) -> (-20.8702, -192)
  line L5 (-18.4351, -194.0433) -> (-28.7197, -206.3)
  line L6 (0, 0) -> (0, -243.31)
  line L7 (-36.4274, -202.4433) -> (-20.8702, -189.3892)
  line L8 (-23.5831, -213.2209) -> (-36.4274, -202.4433)
  line L9 (-13.4288, -195.6332) -> (-23.5831, -213.2209)
  line L10 (-20.8702, -189.3892) -> (-13.4288, -195.6332)
  point P6 (-28.7197, -206.3)
  point P7 (-18.4351, -194.0433)
  point P1 (0, 0)
  point P9 (0, 0)
  point P2 (-24.1234, -210.1567)
  point P5 (-33.3159, -202.4433)
  point P3 (-16, -196.0865)
  point P4 (-20.8702, -192)
  midpoint L1 P6
  midpoint L3 P7
  vertical L6
  perpendicular L1 L5
  perpendicular L3 L5
  coincident P1 P9
  dimension "d378" angle L5 L6 = 40
  dimension "d379" distance P2 P5 = 12
  dimension "d381" distance P6 P7 = 16
  dimension "d382" angle L1 L4 = 80
  dimension "d383" distance P3 L6 = 16
  dimension "d384" distance P1 P4 = 192
  dimension "d388" = 2
extrude "Extrude18" sketch "Sketch12" profile of L1 L2 L3 L4 blind 4
extrude "Extrude19" sketch "Sketch12" profile of L1 L2 L3 L4 L10 L9 L8 L7 blind 2
chamfer "Chamfer14" distance 2
chamfer "Chamfer16" distance 2
mirror "Mirror9" mirrorStitchTolerance 0.1
work_plane "WorkPlane2" AlongDistance -4
split "Split2" bodies "frame-face"
sketch "eye ring" plane through (0, -2, 0) normal (0, -1, 0) x axis (1, 0, 0)
  curve K1 (-21.4074, 148.7715) -> (-6.7192, 141.7849)
  curve K2 (-27.1116, 146.843) -> (-15.7031, 150.6999)
  curve K3 (-23.5683, 155.054) -> (-26.7212, 149.0542)
  curve K4 (-9.8532, 142.9417) -> (-3.5852, 140.628)
  curve K5 (-25.2967, 145.3796) -> (-18.6562, 143.0573)
  curve K6 (-31.3667, 147.0686) -> (-23.997, 145.4169)
  curve K7 (-29.7209, 148.6725) -> (-33.0124, 145.4647)
  curve K8 (-34.7011, 145.394) -> (-37.9154, 149.0197)
  curve K9 (-36.6777, 151.7574) -> (-31.7996, 153.0609)
  curve K10 (-26.2485, 147.1844) -> (-21.7455, 143.6495)
  curve K11 (-10.306, 134.9201) -> (-12.032, 141.1954)
  curve K12 (-1.4553, 138.2606) -> (-7.1754, 134.4759)
  point P10 (-21.4074, 148.7715)
  point P8 (-25.1447, 152.0541)
  point P2 (-6.7192, 141.7849)
  point P7 (-21.9764, 144.2185)
  point P19 (-23.997, 145.4169)
  point P22 (-31.3667, 147.0686)
  point P21 (-36.3082, 147.2068)
  point P20 (-34.2386, 152.4091)
  point P3 (-11.169, 138.0577)
  point P4 (-4.3154, 136.3683)
  midpoint P10 K2
  midpoint P8 K3
  midpoint P2 K4
  midpoint P7 K5
  coincident K1 P19
  midpoint P22 K7
  midpoint P21 K8
  midpoint P20 K9
  midpoint P19 K10
  midpoint P3 K11
  midpoint P4 K12
  dimension "d401" distance = 6
extrude "Extrude11" new body blind 2
thicken "Thicken1" Thickness 1.5
sketch "swirl caps" plane through (0, -4, 0) normal (0, -1, 0) x axis (1, 0, 0)
  curve K1 (-24.9695, 144.2735) -> (-7.2386, 140.3777)
  line L1 (-6.1998, 143.1921) -> (-7.2386, 140.3777)
  curve K2 (-21.8877, 150.1925) -> (-6.1998, 143.1921)
  line L2 (-20.927, 147.3505) -> (-21.8877, 150.1925)
  curve K3 (-20.927, 147.3505) -> (-27.1165, 150.9148)
  curve K4 (-30.3198, 145.9943) -> (-27.1165, 150.9148)
  line L3 (-32.4136, 148.1428) -> (-30.3198, 145.9943)
  curve K5 (-32.4136, 148.1428) -> (-24.9695, 144.2735)
  arc A1 centre (-31.3667, 147.0686) radius 1.5 clockwise from (-32.4136, 148.1428) to (-30.3198, 145.9943)
  arc A2 centre (-21.4074, 148.7715) radius 1.5 clockwise from (-20.927, 147.3505) to (-21.8877, 150.1925)
  arc A3 centre (-6.7192, 141.7849) radius 1.5 clockwise from (-6.1998, 143.1921) to (-7.2386, 140.3777)
  point P8 (-30.3198, 145.9943)
  point P11 (-30.3198, 145.9943)
  point P9 (-32.4136, 148.1428)
  point P10 (-32.4136, 148.1428)
  point P6 (-20.927, 147.3505)
  point P14 (-20.927, 147.3505)
  point P5 (-21.8877, 150.1925)
  point P13 (-21.8877, 150.1925)
  point P4 (-6.1998, 143.1921)
  point P17 (-6.1998, 143.1921)
  point P2 (-7.2386, 140.3777)
  point P16 (-7.2386, 140.3777)
  coincident P8 P11
  coincident P9 P10
  tangent K5 A1
  coincident P6 P14
  coincident P5 P13
  coincident P4 P17
  coincident P2 P16
  tangent K1 A3
extrude "Extrude12" add sketch "swirl caps" profile of L1 L2 L3 A1 A2 A3 against normal blind 2
fillet "Fillet5" radius 1
mirror "Mirror3" mirrorStitchTolerance 0.1 bodies "eye-ring"
extrude "Extrude13" new body sketch "eye ring" along normal blind 3
combine "Combine1"
pipe "Pipe1" SectionSize 4 SectionThickness 1
fillet "Fillet7" radius 2
sketch "Sketch13" plane through (0, -6, 0) normal (0, -1, 0) x axis (1, 0, 0)
  line L1 (-62, 42) -> (-62, 138.2013)
  line L2 (62, 138.2013) -> (62, 42)
  curve K1 (62, 161.7636) -> (62, 138.2013)
  curve K2 (-62, 138.2013) -> (-62, 161.7636)
pipe "Pipe1" SectionSize 5 SectionThickness 1.25
fillet "Fillet9" radius 2.5
move "Move1"
combine "Combine1"
delete_face "DeleteFace1"
mirror "Mirror10" mirrorStitchTolerance 0.1
sketch "Sketch14" plane through (0, -6, 0) normal (0, -1, 0) x axis (1, 0, 0)
  line L1 (-62, 180) -> (-44.4072, 180)
  line L2 (44.4072, 180) -> (62, 180)
  arc A1 centre (0, 168) radius 46 clockwise from (-44.4072, 180) to (44.4072, 180)
pipe "Pipe2" SectionSize 4 SectionThickness 1.25
move "Move2"
offset_faces "OffsetFaces2" distance 2
chamfer "Chamfer17" distance 2
extrude "Extrude20" cut sketch "usb hole" profile of L1 A1 L2 L3 along normal blind 59
offset_faces "OffsetFaces3" distance -2
draft "Draft2" Angle1 45 Angle2 0
draft "Draft3" Angle1 45 Angle2 0
combine "Combine2"
sketch "Sketch15" plane through (0, 0, 0) normal (1, 0, 0) x axis (0, 1, 0)
  curve K1 (-0.5, 161.7636) -> (4.5, 161.7636)
  line L1 (-6, 161.7636) -> (-0.5, 161.7636)
  line L2 (-6, 180) -> (-6, 161.7636)
  line L3 (10, 180) -> (-6, 180)
  line L4 (10, 161.7636) -> (10, 180)
  line L5 (4.5, 161.7636) -> (10, 161.7636)
  line L6 (2, 159.2576) -> (2, 180)
  line L7 (-3.9729, 170.8818) -> (2, 178)
  line L8 (2, 163.7636) -> (-3.9729, 170.8818)
  line L9 (2, 163.7636) -> (7.9729, 170.8818)
  line L10 (7.9729, 170.8818) -> (2, 178)
  point P8 (2, 180)
  point P9 (2, 159.2576)
  point P10 (2, 178)
  point P12 (2, 163.7636)
  point P15 (2, 178)
  point P11 (-3.9729, 170.8818)
  point P13 (7.9729, 170.8818)
  point P14 (2, 163.7636)
  point P2 (4.5, 161.7636)
  midpoint L3 P8
  coincident K1 P9
  perpendicular L3 L6
  coincident L6 P10
  coincident L6 P12
  symmetric L6 P10 P15
  symmetric L6 P11 P13
  symmetric L6 P12 P14
  dimension "d441" angle L6 L8 = 40
  dimension "d442" angle L6 L7 = 40
  dimension "d443" distance P8 P15 = 2
  dimension "d444" distance P2 P14 = 2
